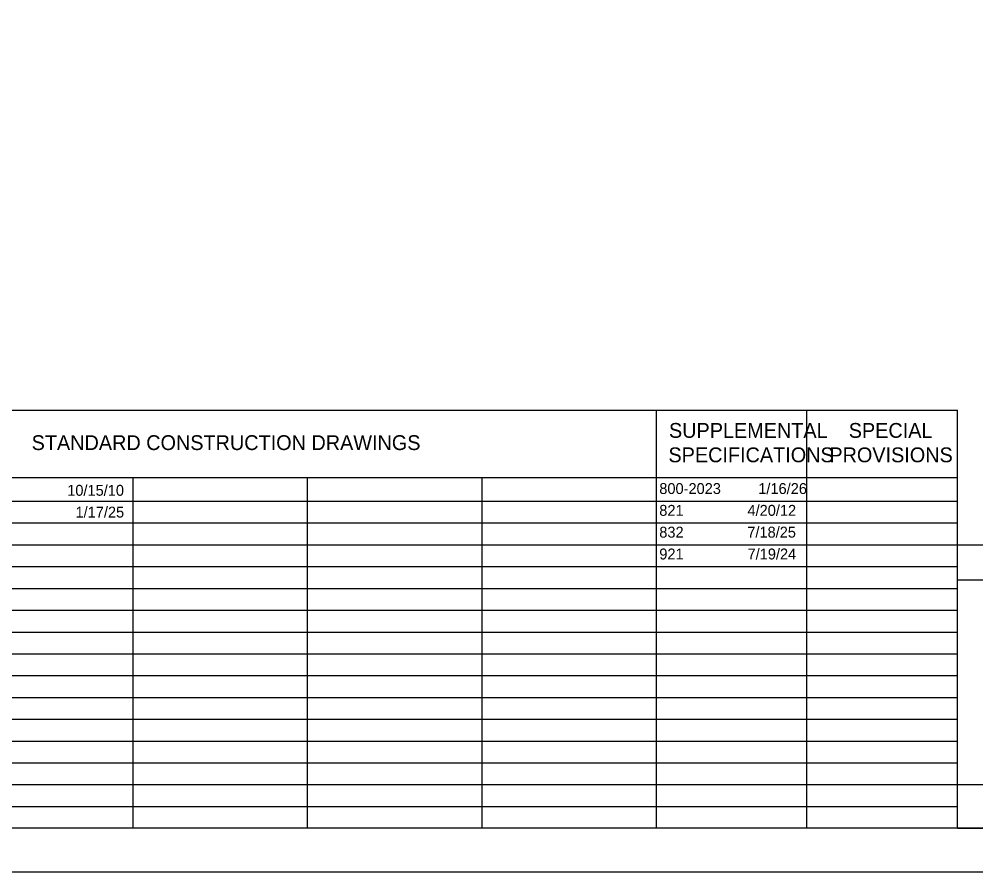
# Model space of a CAD drawing. Extents: x 0 to 34, y 0 to 22.
# Drawn here: x 12.84 to 23.81, y 0 to 9.78 of the extents above; entities that cross this region are included whole.
import ezdxf

# ---------------------------------------------------------------- set-up
doc = ezdxf.new("R2010")
doc.units = 0
for name, color, linetype in [('Default', 7, 'Continuous'), ('SH_Border', 7, 'Continuous'), ('SH_Cut_Line', 7, 'Continuous'), ('SH_Data', 7, 'Continuous'), ('SH_Text', 7, 'Continuous')]:
    doc.layers.add(name, color=color, linetype=linetype)

msp = doc.modelspace()

# ---------------------------------------------------------------- linework, layer by layer
at = {"layer": 'SH_Border'}
msp.add_lwpolyline([(1.5, 21.5), (33.5, 21.5), (33.5, 0.5), (1.5, 0.5)], close=True, dxfattribs=at)
at = {"layer": 'SH_Cut_Line'}
msp.add_lwpolyline([(0, 0), (34, 0), (34, 22), (0, 22)], close=True, dxfattribs=at)
at = {"layer": 'SH_Data'}
for p, q in [((10.15, 5.292), (23.6, 5.292)), ((20.15, 0.5), (20.15, 5.292)), ((21.875, 0.5), (21.875, 5.292)), ((23.6, 0.5), (23.6, 5.292)), ((10.15, 4.521), (23.6, 4.521)), ((14.15, 0.5), (14.15, 4.521)), ((16.15, 0.5), (16.15, 4.521)), ((18.15, 0.5), (18.15, 4.521)), ((10.15, 4.25), (23.6, 4.25)), ((10.15, 4), (23.6, 4)), ((10.15, 3.75), (23.6, 3.75)), ((23.6, 0.5), (23.6, 3.75)), ((23.6, 3.75), (26.4, 3.75)), ((10.15, 3.5), (23.6, 3.5)), ((23.6, 3.35), (26.4, 3.35)), ((10.15, 3.25), (23.6, 3.25)), ((10.15, 3), (23.6, 3)), ((10.15, 2.75), (23.6, 2.75)), ((10.15, 2.5), (23.6, 2.5)), ((10.15, 2.25), (23.6, 2.25)), ((10.15, 2), (23.6, 2)), ((10.15, 1.75), (23.6, 1.75)), ((10.15, 1.5), (23.6, 1.5)), ((10.15, 1.25), (23.6, 1.25)), ((10.15, 1), (23.6, 1)), ((10.15, 0.75), (23.6, 0.75)), ((23.6, 0.5), (26.4, 0.5))]:
    msp.add_line(p, q, dxfattribs=at)
msp.add_lwpolyline([(23.6, 0.5), (23.6, 1), (26.4, 1), (26.4, 0.5)], close=True, dxfattribs=at)

# ---------------------------------------------------------------- texts
at = {"layer": 'Default'}
for s, p in [('10/15/10', (13.394, 4.312)), ('800-2023', (20.182, 4.332)), ('1/16/26', (21.317, 4.332)), ('1/17/25', (13.489, 4.062)), ('821', (20.182, 4.082)), ('4/20/12', (21.193, 4.082)), ('832', (20.182, 3.832)), ('7/18/25', (21.191, 3.832)), ('921', (20.182, 3.582)), ('7/19/24', (21.194, 3.582))]:
    msp.add_text(s, height=0.125, dxfattribs=at).set_placement(p)
at = {"layer": 'SH_Text'}
for s, p in [('SUPPLEMENTAL', (20.293, 4.976)), ('SPECIAL', (22.354, 4.976)), ('STANDARD CONSTRUCTION DRAWINGS', (12.986, 4.836)), ('SPECIFICATIONS', (20.287, 4.696)), ('PROVISIONS', (22.132, 4.696))]:
    msp.add_text(s, height=0.17, dxfattribs=at).set_placement(p)

doc.saveas('drawing.dxf')
